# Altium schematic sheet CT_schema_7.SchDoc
size 274 x 160 mm
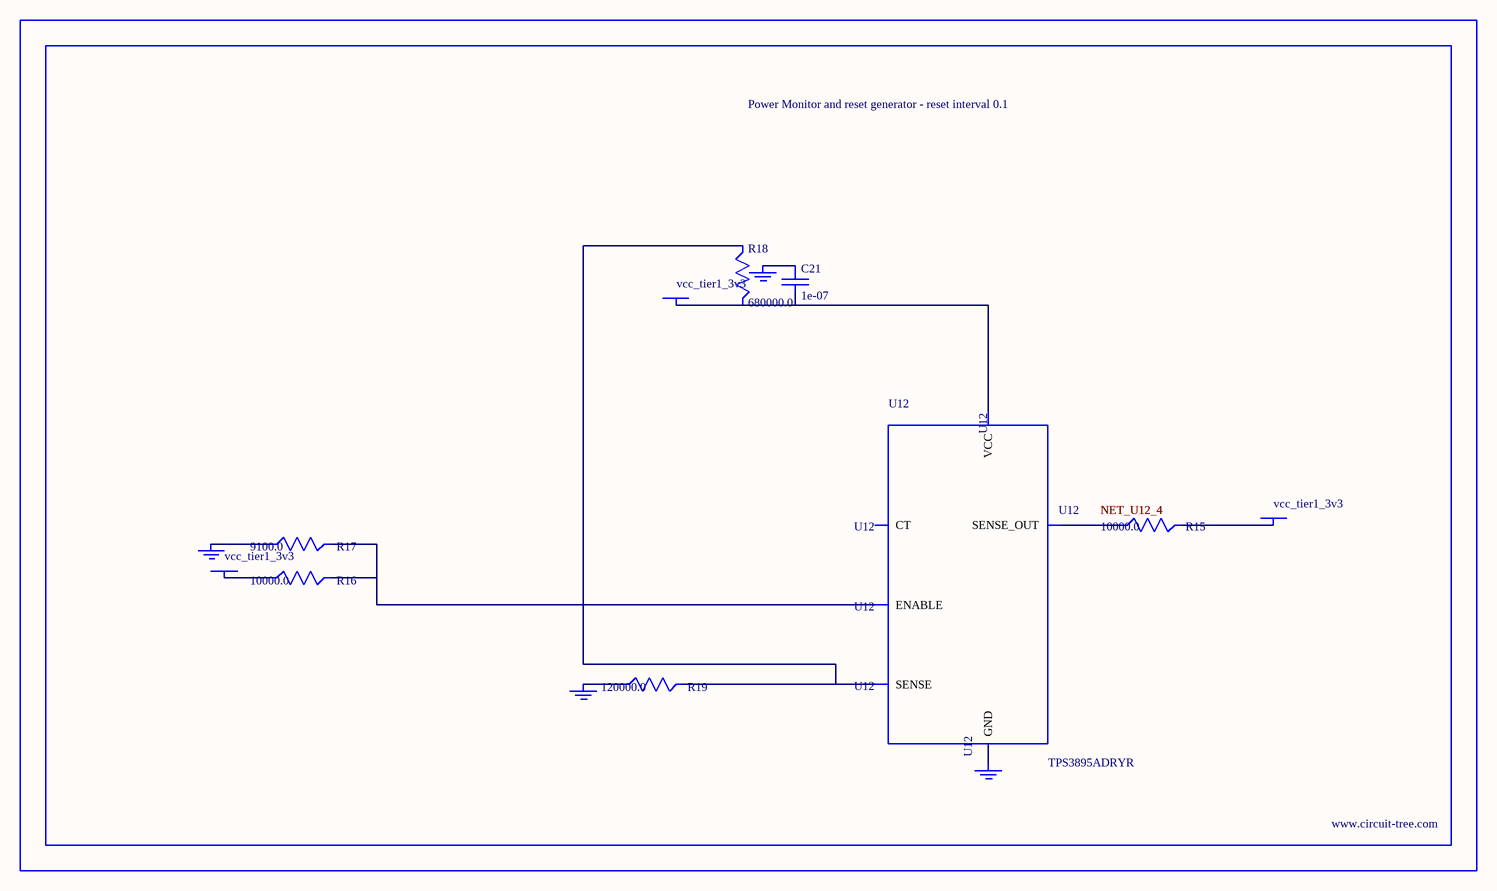
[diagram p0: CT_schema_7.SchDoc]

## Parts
BORDER6  (no value)
C21  1e-07  [C0402]
GND_INSTANCE_6_0  (no value)
GND_INSTANCE_6_1  (no value)
GND_INSTANCE_6_2  (no value)
GND_INSTANCE_6_3  (no value)
POWER_INSTANCE_6_0  vcc_tier1_3v3
POWER_INSTANCE_6_1  vcc_tier1_3v3
POWER_INSTANCE_6_2  vcc_tier1_3v3
R15  10000.0  [R0603]
R16  10000.0  [R0603]
R17  9100.0  [R0603]
R18  680000.0  [R0603]
R19  120000.0  [R0603]
U12  TPS3895ADRYR  [SON-6]

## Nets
NetC21_1: C21.1 GND_INSTANCE_6_2.0(GND)
NetC21_2: C21.2 POWER_INSTANCE_6_2.0(PWR) R18.2 U12.6(VCC)
NetGND_INSTANCE_6_0_0: GND_INSTANCE_6_0.0(GND) R17.1
NetGND_INSTANCE_6_1_0: GND_INSTANCE_6_1.0(GND) R19.1
NetGND_INSTANCE_6_3_0: GND_INSTANCE_6_3.0(GND) U12.2(GND)
NetPOWER_INSTANCE_6_0_0: POWER_INSTANCE_6_0.0(PWR) R16.1
NetPOWER_INSTANCE_6_1_0: POWER_INSTANCE_6_1.0(PWR) R15.2
NetR15_1: R15.1 U12.4(SENSE_OUT)
NetR16_2: R16.2 R17.2 U12.1(ENABLE)
NetR18_1: R18.1 R19.2 U12.3(SENSE)

Not connected (* = marked no-connect by the designer): U12 5(CT)

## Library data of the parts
BORDER6 = BORDER_PAGE6
C21 = C0402C104K3RACTU
GND_INSTANCE_6_0-GND_INSTANCE_6_3 = GND
POWER_INSTANCE_6_0-POWER_INSTANCE_6_2 = PWR
R15 R16 = RC0603JR-0710KL
R17 = RC0603JR-079K1L
R18 = RC0603JR-07680KL
R19 = RC0603JR-07120KL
